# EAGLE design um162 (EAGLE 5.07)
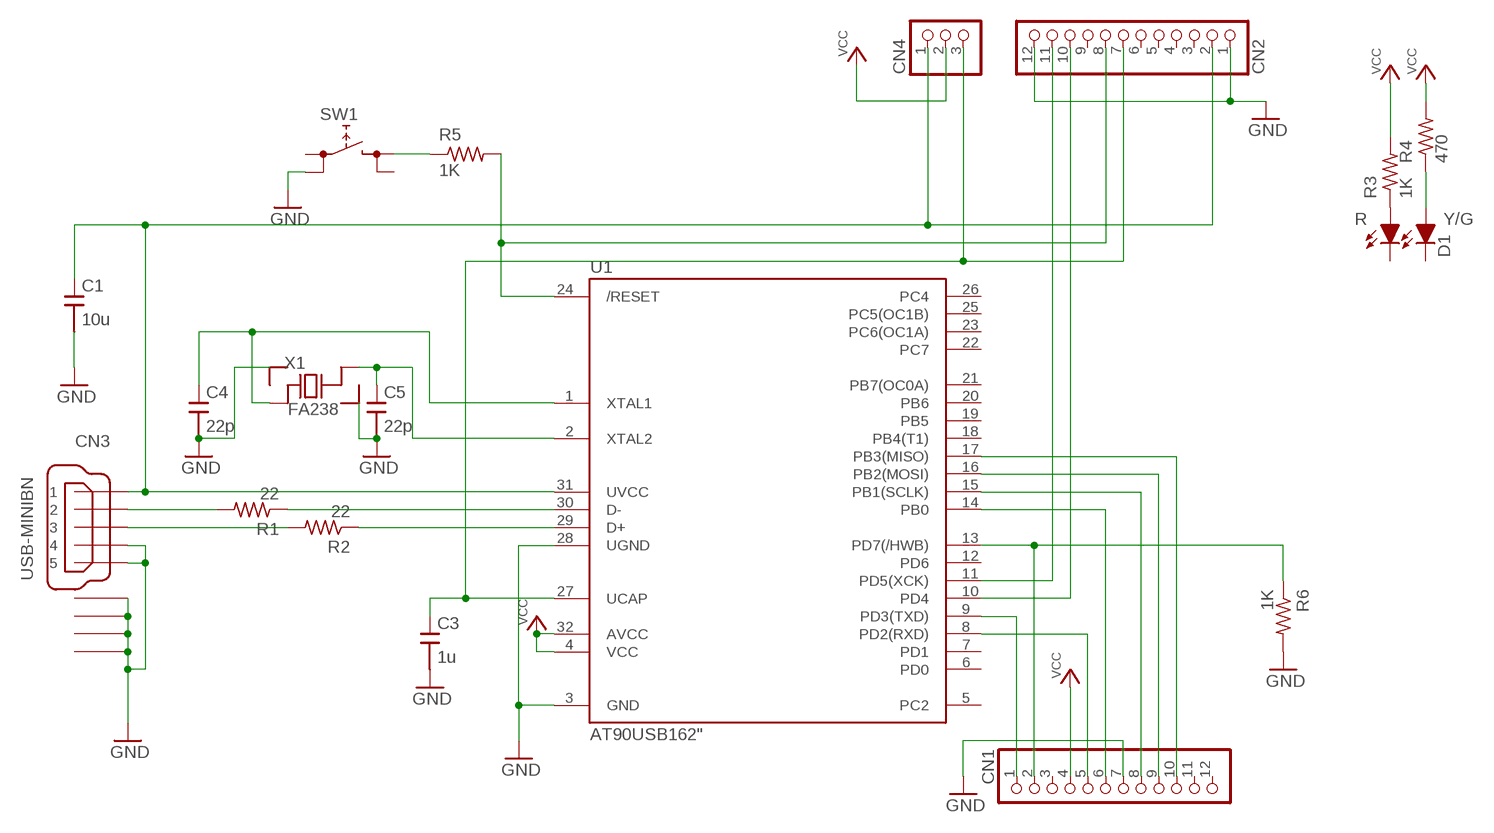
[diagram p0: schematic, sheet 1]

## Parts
C1  10u  C/SMDC2012  [C2012]
C3  1u  C/SMDC1608  [C1608]
C4  22p  C/SMDC3216  [C3216]
C5  22p  C/SMDC3216  [C3216]
CN1  PINHDR12  [PINHDRX12]
CN2  PINHDR12  [PINHDRX12]
CN3  USB-MINIBN  [USB-MINIB-N]
CN4  PINHDR3  [PINHDR1X3]
D1  SEC2XX4  [LED3025]
R1  22  R/SMDR2012  [R2012]
R2  22  R/SMDR2012  [R2012]
R3  1K  R/SMDR2012  [R2012]
R4  470  R/SMDR2012  [R2012]
R5  1K  R/SMDR2012  [R2012]
R6  1K  R/SMDR2012  [R2012]
SW1  TACTSWTACTSW/SMD  [TACTSW/SMD]
U1  AT90USB162"  [TQFP32]
X1  FA238  [FA238]

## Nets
GND [Power]: C1.2 C3.2 C4.2 C5.2 CN1.7 CN2.1 CN2.12 CN3.4 CN3.5 CN3.M1(GND) CN3.M2(GND) CN3.M3(GND) CN3.M4(GND) R6.2 SW1.2 U1.3(GND) U1.28(UGND) X1.2 X1.4
N$1: CN2.11 U1.11(PD5(XCK))
N$2: CN2.10 U1.10(PD4)
N$4: CN1.5 U1.8(PD2(RXD))
N$7: CN1.1 U1.9(PD3(TXD))
N$8: CN2.8 R5.2 U1.24(/RESET)
N$11: CN1.2 R6.1 U1.13(PD7(/HWB))
N$12: CN1.6 U1.14(PB0)
N$13 [Power]: C3.1 CN2.7 CN4.3 U1.27(UCAP)
N$19: CN3.2 R1.2
N$23: D1.3(A1) R3.1
N$24: D1.4(A0) R4.1
N$25: R1.1 U1.30(D-)
N$27: C4.1 U1.1(XTAL1) X1.1
N$28: C5.1 U1.2(XTAL2) X1.3
N$30 [Power]: C1.1 CN2.2 CN3.1 CN4.1 U1.31(UVCC)
N$31: CN1.10 U1.17(PB3(MISO))
N$32: CN1.9 U1.16(PB2(MOSI))
N$33: CN1.8 U1.15(PB1(SCLK))
N$34: CN3.3 R2.2
N$35: R2.1 U1.29(D+)
N$36: R5.1 SW1.3
VCC [Power]: CN1.4 CN4.2 R3.2 R4.2 U1.4(VCC) U1.32(AVCC)
Unconnected: CN1.3 CN1.11 CN1.12 CN2.3 CN2.4 CN2.5 CN2.6 CN2.9 D1.1(C0) D1.2(C1) SW1.1 SW1.4 U1.5(PC2) U1.6(PD0) U1.7(PD1) U1.12(PD6) U1.18(PB4(T1)) U1.19(PB5) U1.20(PB6) U1.21(PB7(OC0A)) U1.22(PC7) U1.23(PC6(OC1A)) U1.25(PC5(OC1B)) U1.26(PC4)

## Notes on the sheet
- R | Y/G

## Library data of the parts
C1 C3-C5 = SRT162-010:C/SMD
CN1 CN2 = SRT162-010:PINHDR12
CN3 = SRT162-010:USB-MINIB
CN4 = SRT162-010:PINHDR3
D1 = SRT162-010:SEC2XX4
R1-R6 = SRT162-010:R/SMD
SW1 = SRT162-010:TACTSW: 4pin tactsw (1,2 - 3,4)
U1 = SRT162-010:AT90USB162: AT90USB162 Atmel AVR
X1 = SRT162-010:FA238

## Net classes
1 Power: width 0.406 mm, clearance 0.203 mm to class 0

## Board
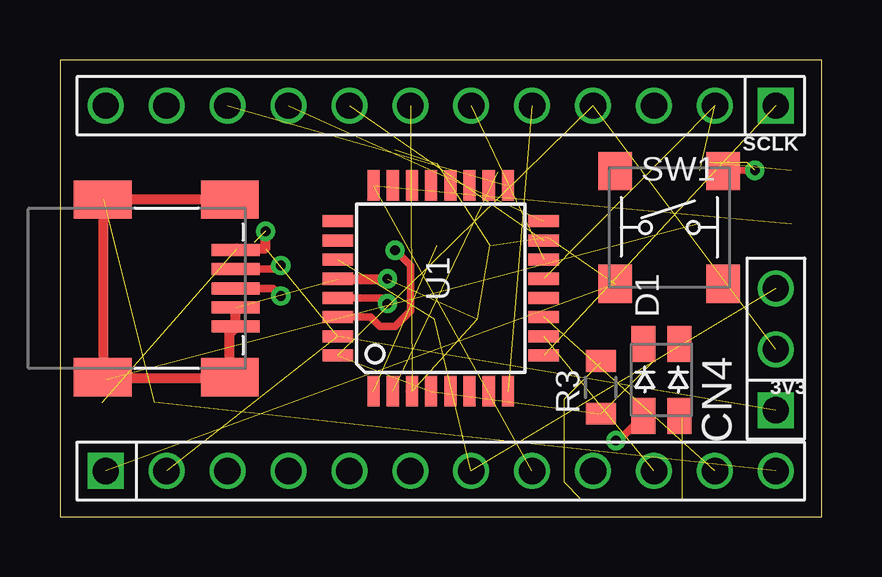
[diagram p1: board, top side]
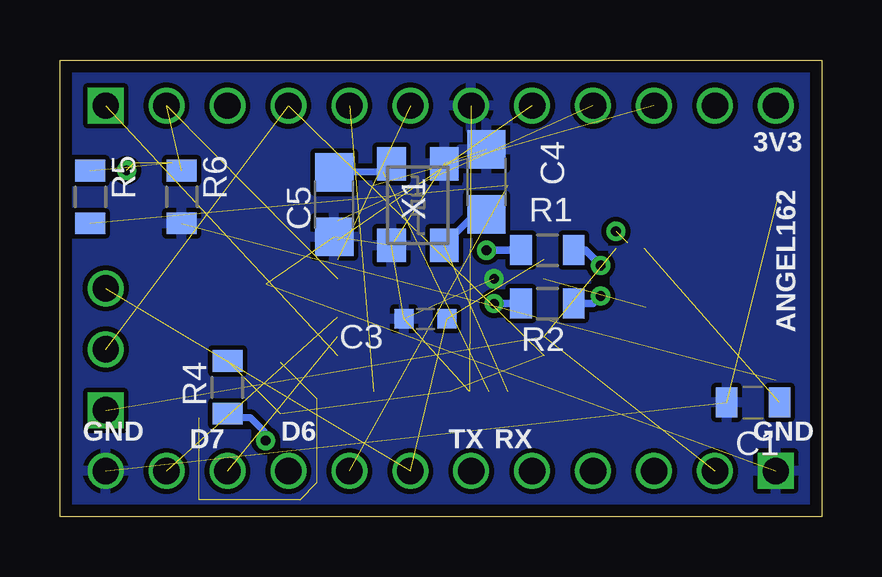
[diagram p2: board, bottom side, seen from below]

Size 31.75 x 19.05 mm. Coordinates in mm from the lower left corner, seen from the top.
Outline: 0,0 31.75,0 31.75,19.05 0,19.05 0,0
Copper layers (1*16): Top 0.0356mm / dielectric 1.5011mm / Bottom 0.0356mm
Design rules "ezpcb-suz": minimum track width 0.3mm, minimum drill 0.4mm, track to track 0.2mm, track to pad 0.235mm, pad to pad 0.2mm, via to via 0.2mm, smd to smd 0.2mm, copper to edge 0.5mm, drill to drill 0.45mm, minimum pad ring 0.2mm, minimum via ring 0.2mm, stop-mask expansion 4mil, vias tented up to drill 0mil, thermal gap 0.2mm
vRestrict: area 20,6.3 to 21.3,12.7; area 12.7,14.3 to 19.1,15.6; area 12.7,3.5 to 19.1,4.8; area 0.3,18.1 to 31.4,18.7; area 0.3,0.3 to 31.4,1; area 31.1,0.3 to 31.7,18.7

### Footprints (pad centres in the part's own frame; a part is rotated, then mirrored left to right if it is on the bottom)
C2012 = smd 0.9 x 1.25: 1 -1.1,0; 2 1.1,0
C1608 = smd 0.8 x 0.8: 1 -0.9,0; 2 0.9,0
C3216 = smd 1.6 x 1.6: 1 -1.35,0; 2 1.35,0
PINHDRX12 = drill 1.1 square: 1 -13.97,0 | drill 1.1 round: 2 -11.43,0; 3 -8.89,0; 4 -6.35,0; 5 -3.81,0; 6 -1.27,0; 7 1.27,0; 8 3.81,0; 9 6.35,0; 10 8.89,0; 11 11.43,0; 12 13.97,0
USB-MINIB-N = smd 2 x 0.5: 1 3.52,1.6; 2 3.52,0.8; 3 3.52,0; 4 3.52,-0.8; 5 3.52,-1.6 | smd 2.4 x 1.6: M1 -2.03,-3.7; M2 -2.03,3.7; M3 3.27,3.7; M4 3.27,-3.7
PINHDR1X3 = drill 1.1 square: 1 -2.54,0 | drill 1.1 round: 2 0,0; 3 2.54,0
LED3025 = smd 1.5 x 1: 1 1.5,0.75; 2 1.5,-0.75; 3 -1.5,-0.75; 4 -1.5,0.75
R2012 = smd 0.9 x 1.25: 1 -1.1,0; 2 1.1,0
TACTSW/SMD = smd 1.4 x 1.6: 1 -2.25,2.35; 2 -2.25,-2.35; 3 2.25,2.35; 4 2.25,-2.35
TQFP32 = smd 1.27 x 0.508: 1 -4.293,2.8; 2 -4.293,2; 3 -4.293,1.2; 4 -4.293,0.4; 5 -4.293,-0.4; 6 -4.293,-1.2; 7 -4.293,-2; 8 -4.293,-2.8; 17 4.293,-2.8; 18 4.293,-2; 19 4.293,-1.2; 20 4.293,-0.4; 21 4.293,0.4; 22 4.293,1.2; 23 4.293,2; 24 4.293,2.8 | smd 0.508 x 1.27: 9 -2.8,-4.293; 10 -2,-4.293; 11 -1.2,-4.293; 12 -0.4,-4.293; 13 0.4,-4.293; 14 1.2,-4.293; 15 2,-4.293; 16 2.8,-4.293; 25 2.8,4.293; 26 2,4.293; 27 1.2,4.293; 28 0.4,4.293; 29 -0.4,4.293; 30 -1.2,4.293; 31 -2,4.293; 32 -2.8,4.293
FA238 = smd 1.4 x 1.2: 1 -1.7,-1.1; 2 1.7,-1.1; 3 1.7,1.1; 4 -1.7,1.1

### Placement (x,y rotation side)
C1  2.86,4.76 180 bottom
C3  16.51,8.26 180 bottom
C4  13.97,13.97 90 bottom
C5  20.32,13.02 270 bottom
CN1  15.88,17.14 180 top
CN2  15.88,1.91 0 top
CN3  3.81,9.53 0 top
CN4  29.84,6.99 90 top
D1  25.08,5.71 90 top
R1  11.43,11.11 0 bottom
R2  11.43,8.89 0 bottom
R3  22.54,5.4 270 top
R4  24.77,5.4 90 bottom
R5  30.48,13.34 270 bottom
R6  26.67,13.34 270 bottom
SW1  25.4,12.06 0 top
U1  15.88,9.53 90 top
X1  16.83,13.02 90 bottom

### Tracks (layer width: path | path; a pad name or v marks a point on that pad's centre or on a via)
GND  (via drill 0.4)  (13 unrouted)
  Top 0.406: CN3.4 CN3.5 7.22,7.78 7.06,7.62 7.06,6.03 CN3.M4 | U1.3 14.61,5.24 | CN3.M4 7.14,5.79 | CN3.M3 7.06,13.26 1.83,13.26 CN3.M2 1.83,13.02 1.83,6.03 CN3.M1 | v13.65,9.92 U1.28 | 1.9,5.71 1.83,5.79 CN3.M1 | CN3.M4 6.91,5.79 2.06,5.79 CN3.M1
  pour Bottom: -0.95,19.68 32.38,19.68 32.38,-0.64 -1.27,-0.64
N$1  (1 unrouted)
N$2  (1 unrouted)
N$4  (1 unrouted)
N$7  (1 unrouted)
N$8  (2 unrouted)
  Top 0.3: U1.24 13.02,13.89
N$11  (2 unrouted)
N$12  (1 unrouted)
N$13  (3 unrouted)
N$19  (via drill 0.4)
  Top 0.305: CN3.2 9.05,10.33 v9.21,10.48
  Bottom 0.305: v9.21,10.48 9.84,11.11 R1.2
N$23  (5 unrouted)
  Top 0.3: 25.96,4.13 25.88,4.21 D1.3 | 22.54,6.43 R3.1
N$24  (via drill 0.4)
  Top 0.305: v23.18,3.17 23.5,3.38 D1.4
  Bottom 0.3: v23.18,3.17 23.18,3.49 23.81,4.13 24.61,4.13 R4.1 | v23.18,3.17
N$25  (via drill 0.4)
  Top 0.305: U1.30 12.95,8.33 13.34,7.94 13.97,7.94 14.61,8.57 14.61,10.48 v13.97,11.11
  Bottom 0.305: v13.97,11.11 R1.1
N$27  (1 unrouted)
  Bottom 0.3: 15.64,11.43 15.72,11.35 | 15.64,11.43 14.53,12.54 14.05,12.54 C4.1 | 15.64,11.43 | X1.1 15.64,11.43
N$28  (1 unrouted)
  Bottom 0.3: C5.1 18.26,14.37 X1.3 | C5.1
N$30  (via drill 0.4)  (5 unrouted)
  Top 0.406: v8.57,11.91 8.57,11.19 7.38,11.19 CN3.1
N$31  (1 unrouted)
N$32  (1 unrouted)
N$33  (1 unrouted)
N$34  (via drill 0.4)
  Top 0.305: CN3.3 8.89,9.53 v9.21,9.21
  Bottom 0.305: v9.21,9.21 9.53,8.89 R2.2
N$35  (via drill 0.4)
  Top 0.305: v13.65,8.89 13.42,9.12 U1.29
  Bottom 0.305: v13.65,8.89 R2.1
N$36  (via drill 0.4)  (3 unrouted)
  Top 0.3: v28.97,14.45 27.7,14.45 SW1.3
VCC  (5 unrouted)

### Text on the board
tPlace: SCLK | 3V3
bPlace: 3V3 | ANGEL162 | GND | D6 | GND | RX | TX | D7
